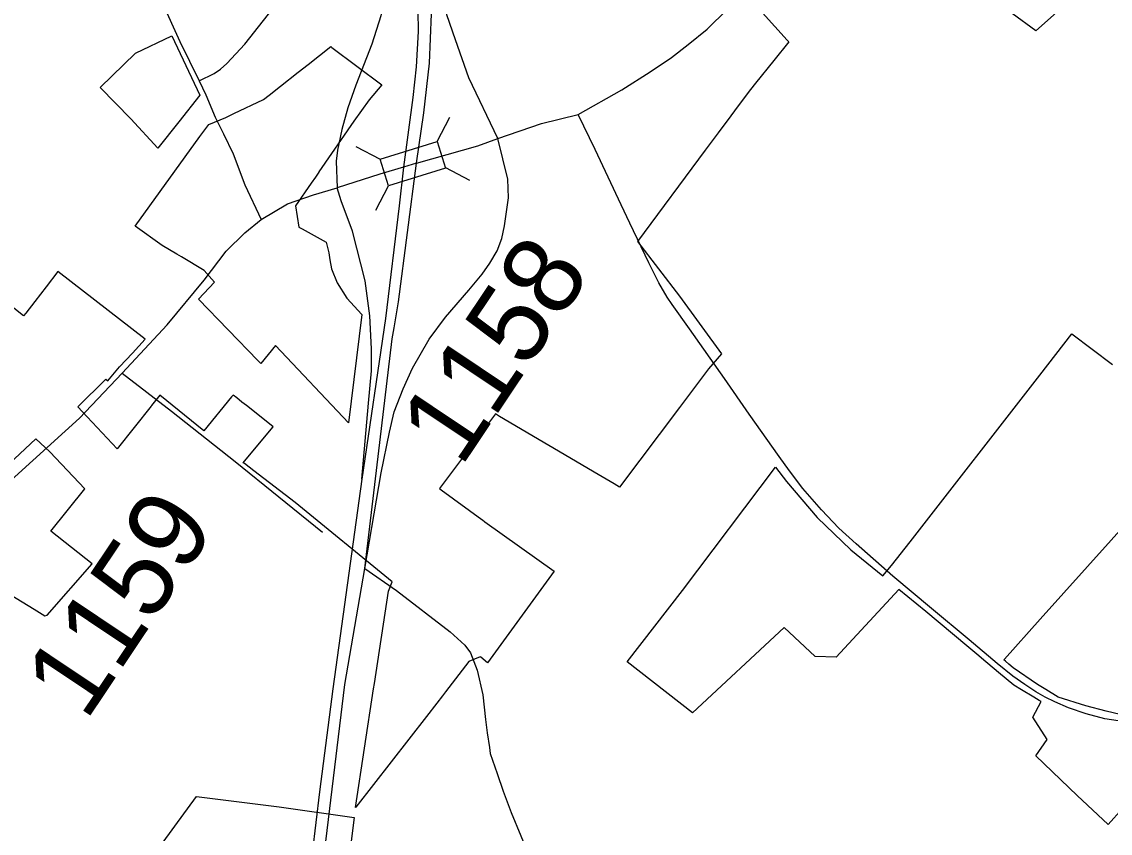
# Model space of a CAD drawing. Extents: x 1716282 to 1717158, y 799307 to 801078.
# Drawn here: x 1716557.2 to 1716655.2, y 800838.9 to 800912 of the extents above; entities that cross this region are included whole.
import ezdxf

# ---------------------------------------------------------------- set-up
doc = ezdxf.new("R2010")
doc.units = 0
for name, color, linetype in [('Exist Boundary Political City Limit New', 7, 'Continuous'), ('Exist Road Primary Interstate Divided Center Attributed', 7, 'Continuous'), ('Exist Road Primary Interstate Ramp 1 Lane Attributed', 7, 'Continuous'), ('Exist Road Secondary Structure Standard Bridge CELL', 7, 'Continuous'), ('Exist Road Secondary Type 51 Attributed', 7, 'Continuous'), ('Map Preparation Boundary City Limit Buffer Line', 7, 'Continuous'), ('Old_Level_1', 7, 'Continuous')]:
    doc.layers.add(name, color=color, linetype=linetype)

msp = doc.modelspace()

# ---------------------------------------------------------------- linework, layer by layer
at = {"layer": 'Exist Boundary Political City Limit New'}
for points in [[(1716653.08, 800915.305), (1716648.52, 800911.218), (1716646.399, 800912.785)], [(1716623.902, 800912.836), (1716626.132, 800910.395), (1716626.282, 800910.233), (1716624.91, 800908.54), (1716623.276, 800906.522), (1716622.814, 800905.951), (1716621.72, 800904.475), (1716621.039, 800903.557), (1716619.91, 800902.036), (1716618.738, 800900.455), (1716612.635, 800892.229), (1716616.435, 800887.324), (1716620.197, 800882.1), (1716619.032, 800880.757), (1716616.418, 800877.281), (1716611.019, 800870.102), (1716610.543, 800870.385), (1716609.094, 800871.241), (1716600.214, 800876.477), (1716599.846, 800876.694), (1716594.8, 800869.976), (1716594.966, 800869.851), (1716598.614, 800867.177), (1716598.668, 800867.138), (1716598.879, 800866.987), (1716605.139, 800862.526), (1716599.133, 800854.277), (1716598.517, 800854.781), (1716598.481, 800854.812), (1716597.465, 800854.376), (1716596.247, 800852.809), (1716595.343, 800851.642), (1716595.077, 800851.3), (1716594.555, 800850.628), (1716593.622, 800849.424), (1716587.274, 800841.244), (1716587.251, 800841.214), (1716588.869, 800851.921), (1716588.943, 800852.405), (1716590.199, 800860.712), (1716590.533, 800861.571), (1716581.808, 800868.729), (1716578.093, 800871.569), (1716577.239, 800872.223), (1716577.13, 800872.305), (1716577.236, 800872.431), (1716579.821, 800875.548), (1716578.732, 800876.412), (1716577.411, 800877.456), (1716577.015, 800877.77), (1716576.552, 800878.136), (1716576.217, 800878.402), (1716576.084, 800878.237), (1716573.573, 800875.18), (1716569.604, 800878.383), (1716568.872, 800877.443), (1716568.841, 800877.405), (1716565.76, 800873.562), (1716563.065, 800876.446), (1716562.218, 800877.323), (1716564.756, 800879.828), (1716564.925, 800879.689), (1716565.988, 800880.943), (1716567.138, 800882.167), (1716568.308, 800883.448), (1716560.424, 800889.523)], [(1716570.702, 800910.785), (1716573.22, 800905.416), (1716571.331, 800903.032), (1716569.441, 800900.643), (1716569.432, 800900.656), (1716567.013, 800903.279), (1716564.236, 800906.132), (1716567.416, 800909.216), (1716570.702, 800910.785)], [(1716585.108, 800909.734), (1716589.615, 800906.354), (1716588.462, 800905.013), (1716587.105, 800903.081), (1716583.945, 800898.506), (1716583.927, 800898.482), (1716583.625, 800898.046), (1716583.252, 800897.504), (1716581.84, 800895.462), (1716582.132, 800893.54), (1716582.435, 800893.369), (1716584.584, 800892.166), (1716584.824, 800891.23), (1716584.933, 800890.598), (1716585.073, 800889.788), (1716585.579, 800888.501), (1716586.453, 800887.121), (1716587.821, 800885.655), (1716586.596, 800875.909), (1716580.045, 800882.855), (1716578.713, 800881.247), (1716578.45, 800881.518), (1716573.085, 800887.035), (1716574.551, 800888.587), (1716573.602, 800889.624), (1716571.563, 800890.848), (1716571.16, 800891.088), (1716569.825, 800891.89), (1716567.399, 800893.609), (1716573.219, 800901.703), (1716574.029, 800902.794), (1716575.555, 800903.428), (1716576.286, 800903.773), (1716578.942, 800905.028), (1716579.45, 800905.427), (1716580.475, 800906.233), (1716582.073, 800907.493), (1716582.967, 800908.197), (1716584.004, 800909.014), (1716585.01, 800909.806), (1716585.08, 800909.753), (1716585.108, 800909.734)], [(1716560.424, 800889.523), (1716559.369, 800888.154), (1716558.341, 800886.824), (1716557.539, 800885.784), (1716557.333, 800885.532), (1716554.811, 800887.522)], [(1716656.32, 800841.149), (1716655.032, 800839.686), (1716652.264, 800842.3), (1716648.512, 800845.894), (1716649.535, 800847.356), (1716648.243, 800849.378), (1716649.003, 800850.774), (1716648.827, 800850.879), (1716648.343, 800851.17), (1716647.228, 800851.835), (1716646.535, 800852.249), (1716645.166, 800853.405), (1716644.775, 800853.735), (1716644.036, 800854.354), (1716643.206, 800855.047), (1716642.315, 800855.79), (1716638.605, 800858.892), (1716636.192, 800860.886), (1716630.534, 800854.78), (1716628.663, 800854.825), (1716625.85, 800857.458), (1716617.601, 800849.745), (1716611.724, 800854.356), (1716616.712, 800860.786), (1716625.068, 800871.891), (1716626.058, 800870.617), (1716628.823, 800867.35), (1716631.852, 800864.446), (1716634.755, 800862.094), (1716635.516, 800863.04), (1716637.199, 800865.169), (1716648.893, 800880.206), (1716651.775, 800883.914), (1716655.442, 800881.152)], [(1716657.252, 800849.336), (1716654.869, 800849.9), (1716653.018, 800850.39), (1716650.549, 800851.176), (1716649.422, 800851.861), (1716648.687, 800852.307), (1716646.494, 800853.821), (1716646.105, 800854.146), (1716645.787, 800854.412), (1716645.653, 800854.524), (1716645.706, 800854.584), (1716648.926, 800858.187), (1716667.832, 800879.268)], [(1716567.588, 800834.896), (1716570.964, 800839.545), (1716572.905, 800842.218), (1716580.352, 800841.278), (1716587.122, 800840.332), (1716586.343, 800834.169)]]:
    msp.add_lwpolyline(points, dxfattribs=at)
at = {"layer": 'Exist Road Primary Interstate Divided Center Attributed'}
for points in [[(1716588.881, 800934.972), (1716590.168, 800931.644), (1716591.055, 800928.695), (1716591.758, 800925.665), (1716592.265, 800922.815), (1716592.639, 800919.43), (1716592.822, 800916.683), (1716592.838, 800914.908), (1716592.899, 800911.15), (1716592.697, 800907.981), (1716592.405, 800905.231), (1716591.573, 800898.947)], [(1716592.721, 800899.289), (1716593.398, 800903.841), (1716593.898, 800908.305), (1716594.083, 800912.742), (1716593.968, 800914.692)], [(1716588.08, 800862.774), (1716590.553, 800883.479), (1716590.731, 800884.452), (1716591.102, 800886.803), (1716592.721, 800899.289)], [(1716591.573, 800898.947), (1716591.184, 800895.445), (1716589.93, 800885.297), (1716587.822, 800870.818)], [(1716587.822, 800870.818), (1716585.204, 800851.93), (1716583.986, 800842.652), (1716582.673, 800831.587), (1716581.7, 800824.23), (1716580.442, 800812.764), (1716579.992, 800808.679), (1716579.873, 800805.67)], [(1716581.108, 800804.065), (1716581.108, 800807.283), (1716581.433, 800813.297), (1716582.211, 800818.355), (1716582.943, 800824.965), (1716583.673, 800830.708), (1716586.287, 800852.305), (1716588.08, 800862.774)]]:
    msp.add_lwpolyline(points, dxfattribs=at)
at = {"layer": 'Exist Road Primary Interstate Ramp 1 Lane Attributed'}
for points in [[(1716588.881, 800934.972), (1716590.181, 800929.215), (1716590.552, 800926.361), (1716590.805, 800923.199), (1716590.8, 800920.537), (1716590.57, 800917.804), (1716590.135, 800915.074), (1716589.53, 800912.576), (1716588.706, 800910.018), (1716587.272, 800906.327), (1716586.565, 800904.298), (1716585.995, 800902.34), (1716585.623, 800900.456), (1716585.498, 800899.473), (1716585.603, 800897.063)], [(1716600.077, 800901.518), (1716597.452, 800906.978), (1716596.236, 800910.427), (1716595.455, 800912.668), (1716594.468, 800917.964), (1716593.976, 800921.344), (1716593.177, 800924.752)], [(1716588.08, 800862.774), (1716589.563, 800871.385), (1716590.307, 800875.063), (1716590.727, 800876.885), (1716591.523, 800878.959), (1716592.38, 800880.814), (1716593.866, 800883.433), (1716595.351, 800885.43), (1716597.437, 800887.839), (1716598.655, 800889.305), (1716599.346, 800890.294), (1716599.997, 800891.398), (1716600.415, 800892.51), (1716600.67, 800893.643), (1716601.009, 800896.185), (1716600.964, 800897.844), (1716600.077, 800901.518)], [(1716587.822, 800870.818), (1716588.401, 800877.657), (1716588.672, 800880.585), (1716588.696, 800882.568), (1716588.531, 800885.552), (1716588.107, 800888.679), (1716586.961, 800893.163), (1716585.942, 800895.889), (1716585.603, 800897.063)]]:
    msp.add_lwpolyline(points, dxfattribs=at)
at = {"layer": 'Exist Road Secondary Structure Standard Bridge CELL'}
for p, q in [((1716594.603, 800901.254), (1716595.743, 800903.436)), ((1716587.273, 800900.793), (1716589.455, 800899.653)), ((1716595.339, 800898.905), (1716597.521, 800897.765)), ((1716589.068, 800895.068), (1716590.208, 800897.249))]:
    msp.add_line(p, q, dxfattribs=at)
msp.add_lwpolyline([(1716589.455, 800899.653), (1716594.6, 800901.265), (1716595.353, 800898.862), (1716590.208, 800897.249)], close=True, dxfattribs=at)
at = {"layer": 'Exist Road Secondary Type 51 Attributed'}
for points in [[(1716573.169, 800906.706), (1716574.514, 800907.367), (1716575.093, 800907.76), (1716575.655, 800908.281), (1716577.266, 800910.028), (1716580.183, 800913.727), (1716584.099, 800918.788), (1716589.587, 800925.8)], [(1716607.303, 800903.686), (1716611.224, 800905.905), (1716613.796, 800907.534), (1716615.721, 800908.822), (1716617.208, 800909.985), (1716618.918, 800911.385), (1716629.713, 800922.016)], [(1716568.448, 800916.979), (1716569.81, 800913.845), (1716571.428, 800910.275), (1716573.169, 800906.706)], [(1716573.169, 800906.706), (1716573.761, 800905.467), (1716574.59, 800903.43), (1716575.359, 800901.936), (1716576.209, 800900.152), (1716577.282, 800897.331), (1716578.751, 800894.216)], [(1716600.077, 800901.518), (1716604.011, 800902.883), (1716607.303, 800903.686)], [(1716655.948, 800849.038), (1716654.74, 800849.224), (1716653.073, 800849.675), (1716651.464, 800850.211), (1716650.234, 800850.763), (1716649.356, 800851.179), (1716648.512, 800851.645), (1716647.526, 800852.305), (1716646.462, 800853.067), (1716645.04, 800854.215), (1716642.515, 800856.324), (1716639.14, 800859.148), (1716635.658, 800862.07), (1716632.34, 800864.979), (1716630.789, 800866.411), (1716629.209, 800868.059), (1716627.534, 800869.967), (1716626.335, 800871.557), (1716625.401, 800872.846), (1716622.709, 800876.691), (1716620.486, 800879.876), (1716617.324, 800884.379), (1716615.774, 800886.548), (1716615.316, 800887.224), (1716614.576, 800888.507), (1716613.672, 800890.318), (1716611.96, 800893.899), (1716611.175, 800895.557), (1716608.836, 800900.517), (1716607.303, 800903.686)], [(1716592.721, 800899.289), (1716598.273, 800900.86), (1716600.077, 800901.518)], [(1716592.721, 800899.289), (1716591.573, 800898.947)], [(1716591.573, 800898.947), (1716589.428, 800898.309), (1716585.603, 800897.063)], [(1716578.751, 800894.216), (1716581.129, 800895.645), (1716583.445, 800896.449), (1716585.603, 800897.063)], [(1716566.233, 800880.381), (1716570.289, 800884.715), (1716573.61, 800888.764), (1716575.599, 800891.364), (1716577.261, 800893.007), (1716578.751, 800894.216)], [(1716503.461, 800839.23), (1716504.294, 800839.999), (1716505.628, 800841.122), (1716507.778, 800842.334), (1716518.175, 800847.387), (1716532.248, 800852.747), (1716537.084, 800854.397), (1716539.475, 800855.403), (1716541.158, 800856.625), (1716542.968, 800858.249), (1716551.202, 800865.888), (1716555.268, 800869.857), (1716562.389, 800876.319), (1716566.233, 800880.381)], [(1716566.233, 800880.381), (1716570.664, 800876.956), (1716576.411, 800872.399), (1716584.263, 800866.032)], [(1716588.08, 800862.774), (1716590.944, 800860.791), (1716595.763, 800857.062), (1716597.085, 800855.851), (1716597.61, 800855.174), (1716598.205, 800853.606), (1716598.703, 800851.372), (1716598.944, 800849.169), (1716599.101, 800847.95), (1716599.319, 800846.638), (1716599.386, 800846.09), (1716600, 800844.289), (1716600.545, 800842.696), (1716601.264, 800840.764), (1716603, 800836.561)]]:
    msp.add_lwpolyline(points, dxfattribs=at)
at = {"layer": 'Map Preparation Boundary City Limit Buffer Line'}
for points in [[(1716570.702, 800910.785), (1716573.22, 800905.416), (1716571.331, 800903.032), (1716569.441, 800900.643), (1716569.432, 800900.656), (1716567.013, 800903.279), (1716564.236, 800906.132), (1716567.416, 800909.216), (1716570.702, 800910.785)], [(1716585.108, 800909.734), (1716589.615, 800906.354), (1716588.462, 800905.013), (1716587.105, 800903.081), (1716583.945, 800898.506), (1716583.927, 800898.482), (1716583.625, 800898.046), (1716583.252, 800897.504), (1716581.84, 800895.462), (1716582.132, 800893.54), (1716582.435, 800893.369), (1716584.584, 800892.166), (1716584.824, 800891.23), (1716584.933, 800890.598), (1716585.073, 800889.788), (1716585.579, 800888.501), (1716586.453, 800887.121), (1716587.821, 800885.655), (1716586.596, 800875.909), (1716580.045, 800882.855), (1716578.713, 800881.247), (1716578.45, 800881.518), (1716573.085, 800887.035), (1716574.551, 800888.587), (1716573.602, 800889.624), (1716571.563, 800890.848), (1716571.16, 800891.088), (1716569.825, 800891.89), (1716567.399, 800893.609), (1716573.219, 800901.703), (1716574.029, 800902.794), (1716575.555, 800903.428), (1716576.286, 800903.773), (1716578.942, 800905.028), (1716579.45, 800905.427), (1716580.475, 800906.233), (1716582.073, 800907.493), (1716582.967, 800908.197), (1716584.004, 800909.014), (1716585.01, 800909.806), (1716585.08, 800909.753), (1716585.108, 800909.734)], [(1716657.252, 800849.336), (1716654.869, 800849.9), (1716653.018, 800850.39), (1716650.549, 800851.176), (1716649.422, 800851.861), (1716648.687, 800852.307), (1716646.494, 800853.821), (1716646.105, 800854.146), (1716645.787, 800854.412), (1716645.653, 800854.524), (1716645.706, 800854.584), (1716648.926, 800858.187), (1716667.832, 800879.268)], [(1716556.132, 800860.423), (1716558.288, 800859.091), (1716559.269, 800858.513), (1716559.466, 800858.574), (1716563.525, 800863.186), (1716559.808, 800866.144), (1716562.856, 800869.944), (1716559.704, 800873.267), (1716558.458, 800874.461), (1716553.574, 800869.915), (1716549.275, 800865.912), (1716549.594, 800865.665), (1716548.352, 800864.452), (1716545.33, 800861.489), (1716546.431, 800860.575), (1716552.031, 800856.333), (1716556.132, 800860.423)]]:
    msp.add_lwpolyline(points, dxfattribs=at)

# ---------------------------------------------------------------- texts
at = {"layer": 'Old_Level_1'}
for s, p in [('1158', (1716596.737, 800871.796)), ('1159', (1716562.953, 800848.915))]:
    msp.add_text(s, height=7.128, rotation=56.20506, dxfattribs=at).set_placement(p)

doc.saveas('drawing.dxf')
